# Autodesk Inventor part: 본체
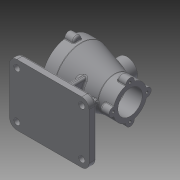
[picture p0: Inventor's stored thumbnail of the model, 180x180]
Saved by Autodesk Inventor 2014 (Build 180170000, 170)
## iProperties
Created: 2020-12
Part Number: 본체
Material: 알루미늄 6061
Document SubType Name: Modeling
Designer: kh
Density: 2.71 g/cm^3
Appearance: 기본값
Mass: 1034.39 g
Surface Area: 852.54 cm^2
Volume: 381.693 cm^3
Author: kh
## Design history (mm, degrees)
sketch "스케치1"
  geometry: L1 (-50, 0)-(50, 0); L2 (-50, 0)-(-50, 44); L3 (-50, 44)-(-30, 44); L4 (-30, 44)-(25, 27.5); L5 (25, 27.5)-(50, 27.5); L6 (50, 27.5)-(50, 0); 1 further point
  constraints: 12 end point, 2 perpendicular, 1 horizontal, 1 midpoint, 1 parallel, 1 vertical
  dimensions: "d0" = 100 distance of L1.start L1.end; "d1" = 50 distance of L1.end point (0, 0); "d2" = 88 diameter of L3 L1; "d3" = 55 diameter of L5 L1; "d4" = 20 distance of L2.end L3.end; "d6" = 25 distance of L4.end L5.end
revolve "회전1" sketch "스케치1" stored, may be unused: angle "d7" = 90 deg
node "작업 평면1"
sketch "스케치2"
  geometry: C1 r 17 at (0, 0); 1 further point
  constraints: 1 centre point, 1 coincident
  dimensions: "d9" = 34 diameter of C1
extrude "돌출1" join sketch "스케치2" stored distance "d10" = 10; taper "d11" = 0 deg
sketch "스케치3"
  geometry: C1 r 14 at (0, 0); 1 further point
  constraints: 1 centre point, 1 coincident
  dimensions: "d12" = 28 diameter of C1
extrude "돌출2" cut sketch "스케치3" distance "d13" = 1; taper "d14" = 0 deg
hole "구멍1" diameter "d17" = 22; stored, may be unused: countersink angle "d21" = 90 deg, drill point angle "d23" = 118 deg; dims "d15" = 10, "d16" = 10, "d18" = 6, "d19" = 4, "d20" = 2, "d22" = 45
chamfer "모따기1" distance "d24" = 1; stored, may be unused: second distance "d25" = 2, angle "d26" = 45 deg
sketch "스케치4"
  geometry: L1 (-50, -44)-(-50, 44) reference; L2 (-30, -44)-(-30, 44) reference; L3 (50, -27.5)-(50, 27.5) reference; L4 (-50, 0)-(50, 0); L5 (-50, 32)-(-27, 32); L6 (-27, 32)-(-27, 26); L7 (-27, 26)-(20, 26); L8 (20, 26)-(20, 20); L9 (20, 20)-(50, 20); 1 further point
  constraints: 12 end point, 3 parallel, 2 midpoint, 2 perpendicular, 2 point on line
  dimensions: "d27" = 64 diameter of L5 L4; "d28" = 23 distance between parallel lines of L1 L6; "d29" = 52 diameter of L7 L4; "d30" = 30 distance between parallel lines of L3 L8; "d31" = 40 diameter of L9 L4
  node "투영된 루프1"
node "작업 평면2"
sketch "스케치5"
  geometry: L1 (-65, 50)-(65, 50); L2 (65, 50)-(65, -50); L3 (65, -50)-(-65, -50); L4 (-65, -50)-(-65, 50); C1 r 11 at (0, 0) reference; 1 further point
  constraints: 8 end point, 2 parallel, 1 horizontal, 1 perpendicular
  dimensions: "d34" = 100 distance between parallel lines of L1 L3; "d35" = 130 distance between parallel lines of L4 L2; "d36" = 65 distance from line of L2 point (0, 0); "d37" = 50 distance from line of point (0, 0) L1
extrude "돌출3" join sketch "스케치5" distance "d38" = 12; taper "d39" = 0 deg
sketch "스케치6"
  geometry: L1 (-50, -44)-(-30, -44) reference; L2 (-30, -44)-(25, -27.5) reference; L3 (25, -27.5)-(50, -27.5) reference; L4 (65, -70)-(-65, -70) reference; L5 (-24, -40.112)-(-24, -70); L6 (24, -25.712)-(24, -70); L7 (-24, -40.112)-(24, -25.712); 1 further point
  constraints: 6 end point, 2 perpendicular, 2 point on line, 1 parallel
  dimensions: "d40" = 2 distance between parallel lines of L2 L7; "d41" = 48 distance between parallel lines of L6 L5; "d42" = 24 distance from line of point (0, 0) L5
extrude "돌출4" join sketch "스케치6" stored distance "d43" = 8; taper "d44" = 0 deg
sketch "스케치7"
  geometry: L1 (-70, -50)-(-70, 50) reference; L2 (-70, 25)-(-15, 25); L3 (-15, 25)-(-15, -25); L4 (-15, -25)-(-70, -25); 1 further point
  constraints: 6 end point, 2 perpendicular, 2 point on line, 1 parallel
  dimensions: "d45" = 50 distance between parallel lines of L2 L4; "d46" = 25 distance from line of point (0, 0) L2; "d47" = 55 distance between parallel lines of L1 L3
extrude "돌출5" join sketch "스케치7" stored distance "d48" = 8; taper "d49" = 0 deg
revolve "회전3" stored, may be unused: angle "d50" = 90 deg
sketch "스케치8"
  geometry: C1 r 7 at (0, 44); 2 further points
  constraints: 2 vertical alignment, 1 centre point, 1 other
  dimensions: "d51" = 14 diameter of C1
extrude "돌출6" join sketch "스케치8" distance "d52" = 15; taper "d53" = 0 deg
fillet "모깎기1" dims "d54" = 3
fillet "모깎기2" dims "d55" = 1
sketch "스케치9"
  geometry: C1 r 7 at (0, 27.5); 2 further points
  constraints: 2 vertical alignment, 1 centre point, 1 other
  dimensions: "d59" = 14 diameter of C1
extrude "돌출7" join sketch "스케치9" distance "d60" = 15; taper "d61" = 0 deg
fillet "모깎기3" dims "d62" = 3
fillet "모깎기4" dims "d63" = 1
hole "구멍2" diameter "d69" = 4.134; stored, may be unused: countersink angle "d73" = 90 deg, drill point angle "d75" = 118 deg; dims "d67" = 10, "d68" = 10, "d70" = 9, "d71" = 4, "d72" = 2, "d74" = 11
hole "구멍3" diameter "d81" = 4.134; stored, may be unused: countersink angle "d85" = 90 deg, drill point angle "d87" = 118 deg; dims "d79" = 10, "d80" = 10, "d82" = 9, "d83" = 4, "d84" = 2, "d86" = 11
fillet "모깎기5" dims "d91" = 3
fillet "모깎기8" dims "d94" = 1
fillet "모깎기9" dims "d95" = 12
hole "구멍4" diameter "d98" = 10; stored, may be unused: countersink angle "d102" = 90 deg, drill point angle "d104" = 118 deg; dims "d96" = 10, "d97" = 10, "d99" = 9, "d100" = 4, "d101" = 2, "d103" = 11
sketch "스케치10"
  geometry: L1 (7, 4)-(21, 4) reference; L2 (24, 1)-(24, -1) reference; L3 (21, -4)-(7, -4) reference; L4 (4, -7)-(4, -22) reference; L5 (1, -25)-(-1, -25) reference; L6 (-4, -22)-(-4, -7) reference; L7 (-7, -4)-(-21, -4) reference; L8 (-24, -1)-(-24, 1) reference; L9 (-21, 4)-(-7, 4) reference; L10 (-4, 7)-(-4, 22) reference; L11 (-1, 25)-(1, 25) reference; L12 (4, 22)-(4, 7) reference; L13 (-65, 38)-(-65, -38) reference; L14 (-53, -50)-(53, -50) reference; L15 (65, -38)-(65, 38) reference; L16 (53, 50)-(-53, 50) reference; L17 (20, 26)-(20, -26) reference; L18 (-27, 26)-(-27, -26) reference; C1 r 5 at (-53, 38) reference; C2 r 5 at (-53, -38) reference; C3 r 5 at (53, 38) reference; C4 r 5 at (53, -38) reference; A1 r 3 centre (7, 7) between (4, 7) and (7, 4) reference; A2 r 3 centre (21, 1) between (24, 1) and (21, 4) reference; A3 r 3 centre (21, -1) between (21, -4) and (24, -1) reference; A4 r 3 centre (7, -7) between (7, -4) and (4, -7) reference; A5 r 3 centre (1, -22) between (1, -25) and (4, -22) reference; A6 r 3 centre (-1, -22) between (-4, -22) and (-1, -25) reference; A7 r 3 centre (-7, -7) between (-4, -7) and (-7, -4) reference; A8 r 3 centre (-21, -1) between (-24, -1) and (-21, -4) reference; A9 r 3 centre (-21, 1) between (-21, 4) and (-24, 1) reference; A10 r 3 centre (-7, 7) between (-7, 4) and (-4, 7) reference; A11 r 3 centre (-1, 22) between (-1, 25) and (-4, 22) reference; A12 r 3 centre (1, 22) between (4, 22) and (1, 25) reference; A13 r 12 centre (-53, 38) between (-53, 50) and (-65, 38) reference; A14 r 12 centre (-53, -38) between (-65, -38) and (-53, -50) reference; A15 r 12 centre (53, -38) between (53, -50) and (65, -38) reference; A16 r 12 centre (53, 38) between (65, 38) and (53, 50) reference; 3 further points
  constraints: 1 vertical alignment, 2 other
  dimensions: "d109" = 10 distance from line of L14 point (0, -40)
feature "엠보싱1" sketch "스케치10" dims "d110" = 0.5, "d111" = 0
fillet "모깎기10" dims "d112" = 3
fillet "모깎기11" dims "d113" = 3
fillet "모깎기12" dims "d114" = 3
fillet "모깎기13" dims "d115" = 3
fillet "모깎기14" dims "d116" = 3
fillet "모깎기15" dims "d117" = 3
node "솔리드1"
pattern_circular "원형 패턴1" dims "d57" = 360 deg
pattern_circular "원형 패턴2" dims "d65" = 360 deg
pattern_circular "원형 패턴3" dims angle "d77" = 360 deg
pattern_circular "원형 패턴4" dims angle "d89" = 360 deg
pattern_linear "직사각형 패턴1"
node "투영된 루프2"
node "투영된 루프3"
other parameters: "d8" = 45, "d33" = -82
